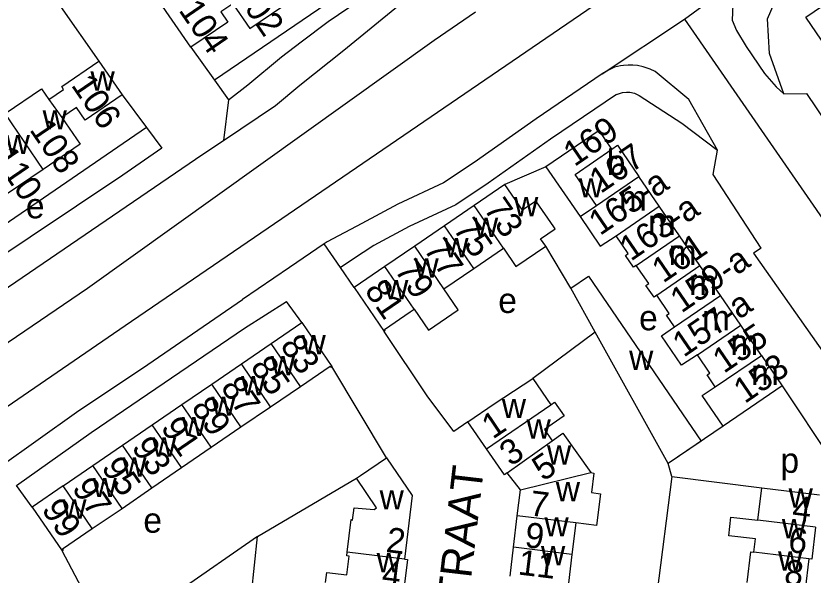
# Model space of a CAD drawing. Extents: x 157569 to 159501, y 382907 to 384670.
# Drawn here: x 158251.5 to 158378.5, y 383372.1 to 383461.2 of the extents above; entities that cross this region are included whole.
import ezdxf

# ---------------------------------------------------------------- set-up
doc = ezdxf.new("R2010")
doc.units = 0
for name, color, linetype in [('BLT_Basislijn', 7, 'Continuous'), ('BLT_Bebouwing', 7, 'Continuous'), ('BLT_Centroide', 7, 'Continuous'), ('BLT_Huisnummer', 7, 'Continuous'), ('BLT_Huisnummer_ tussenligend', 7, 'Continuous'), ('BLT_Huisnummer_reeks', 7, 'Continuous'), ('BLT_Onderverdeling_panden', 7, 'Continuous'), ('BLT_Straatnaam', 7, 'Continuous'), ('BLT_Vlakafsluiter', 7, 'Continuous')]:
    doc.layers.add(name, color=color, linetype=linetype)

msp = doc.modelspace()

# ---------------------------------------------------------------- linework, layer by layer
at = {"layer": 'BLT_Basislijn'}
for p, q in [((158268.87, 383411.85), (158344.6, 383463.62)), ((158358.02, 383460.71), (158395.45, 383406.45)), ((158268.41, 383448.63), (158272.26, 383443.46)), ((158285.33, 383447.86), (158284.53, 383441.35)), ((158272.26, 383443.46), (158229.21, 383413.95)), ((158272.26, 383443.46), (158274.71, 383440.16)), ((158335.92, 383437.19), (158329.36, 383434.34)), ((158303.19, 383421.09), (158300.61, 383424.9)), ((158339.89, 383417.82), (158335.88, 383424.52)), ((158305.35, 383417.9), (158303.19, 383421.09)), ((158297.04, 383412.33), (158294.59, 383415.71)), ((158343.78, 383410.81), (158333.82, 383403.43)), ((158310.53, 383390.76), (158301.83, 383405.34)), ((158373.58, 383402.22), (158383.14, 383387.77)), ((158364.17, 383395.83), (158355.41, 383389.85)), ((158355.97, 383387.8), (158355.41, 383389.85)), ((158289.96, 383378.2), (158305.74, 383387.52)), ((158355.97, 383387.8), (158345.24, 383302.74)), ((158355.97, 383387.8), (158370.3, 383385.97)), ((158254.07, 383382.91), (158251.55, 383386.37)), ((158288.29, 383362.43), (158289.96, 383378.2)), ((158264.43, 383365.32), (158258.86, 383375.92))]:
    msp.add_line(p, q, dxfattribs=at)
for points in [[(158285.33, 383447.86), (158288.45, 383450.24), (158293.8, 383454.7), (158296.92, 383457.08), (158301.23, 383460.35), (158320.69, 383473.57), (158328.86, 383479.81), (158330.2, 383481.6), (158330.5, 383484.12), (158328.86, 383492.74), (158329.57, 383494.21)], [(158328.23, 383488.92), (158329.02, 383482.29), (158283.13, 383450.96)], [(158284.53, 383441.35), (158292.81, 383446.92), (158296.69, 383450.16), (158303.7, 383455.76), (158312.43, 383462.88), (158315.66, 383465.79), (158332.42, 383477.98)], [(158251.08, 383470.55), (158252.5, 383471.5), (158264.68, 383454)], [(158368.7, 383468.6), (158367.49, 383467.29), (158366.26, 383465.41), (158365.68, 383463.03), (158365.61, 383460.57), (158366.26, 383458.9), (158367.85, 383456.37), (158370.74, 383452.03), (158372.62, 383449.93), (158373.85, 383448.78)], [(158373.85, 383448.78), (158371.56, 383455.24), (158371.21, 383460.74), (158372.45, 383463.58), (158373.64, 383464.73)], [(158262.9, 383417.82), (158318.11, 383457.34), (158324.71, 383461.89)], [(158279.37, 383456.24), (158283.13, 383450.96)], [(158353.35, 383452.34), (158352.55, 383452.72), (158351.4, 383453.1), (158350.49, 383453.3), (158349.78, 383453.38), (158349.01, 383453.38), (158348.3, 383453.34), (158347.8, 383453.28), (158346.87, 383453.04), (158346.4, 383452.86), (158345.87, 383452.59), (158344.89, 383451.99)], [(158363.23, 383439.81), (158358.69, 383447.92), (158353.35, 383452.34)], [(158283.13, 383450.96), (158285.33, 383447.86)], [(158344.89, 383451.99), (158334.37, 383444.84), (158324.48, 383437.86), (158319.61, 383434.62), (158312.32, 383431.21), (158306.58, 383428.12)], [(158347.14, 383448.68), (158336.64, 383441.55), (158326.74, 383434.56), (158321.58, 383431.12), (158314.11, 383427.64), (158308.48, 383424.6)], [(158347.14, 383448.68), (158348.11, 383449.04), (158348.74, 383449.07), (158349.28, 383449.07), (158350.01, 383448.92), (158350.76, 383448.55)], [(158350.76, 383448.55), (158357.59, 383444.14), (158363.23, 383439.81)], [(158373.85, 383448.78), (158377.46, 383448.87)], [(158377.46, 383448.87), (158385.58, 383436.8), (158387.08, 383434.08), (158401.15, 383413.79), (158401.36, 383413.55)], [(158281.28, 383439.16), (158284.53, 383441.35)], [(158274.71, 383440.16), (158268.52, 383435.84), (158231.56, 383411.11)], [(158370.2, 383424.2), (158362.58, 383435.92), (158363.23, 383439.81)], [(158191.06, 383377.09), (158244.7, 383414.23), (158281.28, 383439.16)], [(158306.58, 383428.12), (158301.08, 383425.22), (158300.61, 383424.9)], [(158300.61, 383424.9), (158295.08, 383421.12), (158287.59, 383416.02)], [(158308.48, 383424.6), (158306.79, 383423.5), (158303.19, 383421.09)], [(158370.2, 383424.2), (158369, 383423.38)], [(158369, 383423.38), (158386.7, 383398.24), (158386.5, 383396.7), (158383.14, 383387.77)], [(158094.46, 383303.58), (158123.76, 383323.12), (158150.88, 383341.57), (158262.9, 383417.82)], [(158261.15, 383398.07), (158272.49, 383405.62), (158287.59, 383416.02)], [(158263.46, 383394.8), (158287.89, 383411.42), (158294.59, 383415.71)], [(158100.7, 383295.99), (158125.39, 383313.08), (158140.85, 383323.93), (158268.87, 383411.85)], [(158323.49, 383396.53), (158321.27, 383394.94), (158316.98, 383400.65), (158310.13, 383410.92)], [(158131.9, 383308.9), (158138.33, 383313.42), (158187.3, 383347.02), (158228.07, 383374.98), (158248.84, 383389.35), (158261.15, 383398.07)], [(158251.55, 383386.37), (158263.46, 383394.8)], [(158289.96, 383378.2), (158277.29, 383369.4), (158274.72, 383365.15), (158273.9, 383364.16)]]:
    msp.add_lwpolyline(points, dxfattribs=at)
at = {"layer": 'BLT_Bebouwing'}
for p, q in [((158279.37, 383456.24), (158273.85, 383464.21)), ((158335.92, 383437.19), (158341.36, 383429.22)), ((158255.83, 383436.75), (158249.95, 383432.73)), ((158353.98, 383430.89), (158350.74, 383435.64)), ((158329.36, 383434.34), (158324.49, 383431.01)), ((158324.49, 383431.01), (158319.75, 383427.76)), ((158357.21, 383426.17), (158353.98, 383430.89)), ((158319.75, 383427.76), (158315.02, 383424.52)), ((158360.46, 383421.41), (158357.21, 383426.17)), ((158315.02, 383424.52), (158310.28, 383421.27)), ((158324.41, 383420.96), (158329.15, 383424.2)), ((158310.28, 383421.27), (158305.35, 383417.9)), ((158319.67, 383417.71), (158324.41, 383420.96)), ((158363.71, 383416.66), (158360.46, 383421.41)), ((158305.35, 383417.9), (158310.13, 383410.92)), ((158343.78, 383410.81), (158339.89, 383417.82)), ((158366.96, 383411.9), (158363.71, 383416.66)), ((158370.25, 383407.09), (158366.96, 383411.9)), ((158355.41, 383389.85), (158343.78, 383410.81)), ((158287.4, 383405.73), (158292.14, 383408.97)), ((158370.25, 383407.09), (158373.58, 383402.22)), ((158282.67, 383402.49), (158287.4, 383405.73)), ((158333.82, 383403.43), (158336.71, 383399.23)), ((158277.93, 383399.25), (158282.67, 383402.49)), ((158292.06, 383398.92), (158296.8, 383402.16)), ((158273.2, 383396), (158277.93, 383399.25)), ((158287.33, 383395.68), (158292.06, 383398.92)), ((158326.47, 383392.21), (158323.49, 383396.53)), ((158268.46, 383392.76), (158273.2, 383396)), ((158282.59, 383392.44), (158287.33, 383395.68)), ((158263.73, 383389.52), (158268.46, 383392.76)), ((158360.65, 383393.44), (158355.41, 383389.85)), ((158277.86, 383389.2), (158282.59, 383392.44)), ((158258.99, 383386.28), (158263.73, 383389.52)), ((158273.12, 383385.96), (158277.86, 383389.2)), ((158331.87, 383385.68), (158329.76, 383388.37)), ((158268.39, 383382.71), (158273.12, 383385.96)), ((158331.36, 383381.51), (158331.87, 383385.68)), ((158369.67, 383380.85), (158370.3, 383385.97)), ((158370.3, 383385.97), (158379.51, 383384.84)), ((158263.65, 383379.47), (158268.39, 383382.71)), ((158330.75, 383376.5), (158331.36, 383381.51)), ((158340.67, 383380.38), (158340.06, 383375.37)), ((158330.2, 383371.91), (158330.75, 383376.5)), ((158340.06, 383375.37), (158339.5, 383370.78)), ((158377.82, 383374.66), (158377.22, 383369.76))]:
    msp.add_line(p, q, dxfattribs=at)
for points in [[(158380.64, 383456.2), (158377.33, 383461.04), (158384.13, 383465.7), (158387.08, 383461.39), (158387.44, 383460.86)], [(158286.02, 383463.18), (158284.12, 383461.87), (158285.22, 383460.25), (158279.37, 383456.24)], [(158286.02, 383463.18), (158288.75, 383459.2), (158293.82, 383462.68)], [(158256.72, 383447.9), (158259.08, 383449.51), (158258.77, 383449.96), (158264.68, 383454)], [(158264.68, 383454), (158268.41, 383448.63)], [(158249.76, 383445.65), (158255.56, 383449.6), (158256.72, 383447.9)], [(158268.41, 383448.63), (158262.52, 383444.6), (158261.12, 383446.64), (158258.79, 383445.05)], [(158258.79, 383445.05), (158261.72, 383440.77), (158255.83, 383436.75)], [(158346.43, 383439.97), (158344.38, 383442.96), (158335.92, 383437.19)], [(158346.43, 383439.97), (158347.35, 383440.6), (158350.74, 383435.64)], [(158335.88, 383424.52), (158335.07, 383425.71), (158337.37, 383427.28), (158337.16, 383427.58), (158334.43, 383431.56), (158334.33, 383431.71), (158332.17, 383430.23), (158329.36, 383434.34)], [(158341.36, 383429.22), (158344.57, 383424.53), (158347.11, 383426.15)], [(158350.32, 383421.44), (158349.89, 383421.15), (158348.61, 383423.03), (158349.04, 383423.32), (158347.11, 383426.15)], [(158329.15, 383424.2), (158331.12, 383421.27), (158335.88, 383424.52)], [(158353.57, 383416.68), (158353.14, 383416.39), (158351.86, 383418.26), (158352.29, 383418.56), (158350.32, 383421.44)], [(158339.89, 383417.82), (158342.69, 383419.73), (158360.65, 383393.44)], [(158314.93, 383414.47), (158317.19, 383411.1), (158321.93, 383414.34), (158319.67, 383417.71)], [(158356.39, 383411.64), (158355.12, 383413.49), (158355.55, 383413.78), (158353.57, 383416.68)], [(158310.13, 383410.92), (158310.32, 383411.05), (158310.19, 383411.23), (158314.27, 383414.02), (158314.93, 383414.47)], [(158292.14, 383408.97), (158297.04, 383412.33)], [(158297.04, 383412.33), (158301.83, 383405.34)], [(158360.07, 383407.17), (158357.53, 383405.54), (158354.33, 383410.24), (158356.39, 383411.64)], [(158362.89, 383402.11), (158361.61, 383403.98), (158362.04, 383404.28), (158360.07, 383407.17)], [(158296.8, 383402.16), (158301.52, 383405.4), (158301.65, 383405.22), (158301.83, 383405.34)], [(158323.49, 383396.53), (158327.7, 383399.38), (158333.82, 383403.43)], [(158364.17, 383395.83), (158360.83, 383400.71), (158362.89, 383402.11)], [(158373.58, 383402.22), (158369.5, 383399.47), (158364.17, 383395.83)], [(158336.71, 383399.23), (158337.31, 383399.63), (158338.82, 383397.44), (158335.68, 383395.27), (158336.93, 383393.45)], [(158336.93, 383393.45), (158338.64, 383394.67), (158343.05, 383388.4)], [(158329.76, 383388.37), (158329.33, 383388.03), (158326.47, 383392.21)], [(158305.74, 383387.52), (158306.39, 383387.96), (158310.53, 383390.76)], [(158310.53, 383390.76), (158314.6, 383384.74), (158313.37, 383374.6)], [(158304.25, 383375.71), (158304.89, 383380.95), (158305.12, 383380.84), (158305.36, 383382.8), (158308.58, 383382.54), (158308.93, 383382.79), (158305.74, 383387.52)], [(158343.05, 383388.4), (158343.58, 383388.32), (158343.2, 383385.21), (158344.6, 383385.04), (158343.99, 383379.98), (158340.67, 383380.38)], [(158258.99, 383386.28), (158254.07, 383382.91)], [(158254.07, 383382.91), (158258.86, 383375.92)], [(158369.04, 383375.73), (158369.3, 383377.83), (158365.04, 383378.35), (158365.39, 383381.28), (158369.67, 383380.85)], [(158258.86, 383375.92), (158259.04, 383376.05), (158258.92, 383376.23), (158263.65, 383379.47)], [(158378.88, 383379.72), (158378.26, 383374.61), (158377.82, 383374.66)], [(158304.22, 383372.1), (158304.59, 383375.09), (158304.18, 383375.14), (158304.25, 383375.71)], [(158367.99, 383370.89), (158368.59, 383375.79), (158369.04, 383375.73)], [(158313.37, 383374.6), (158313.86, 383374.54), (158313.23, 383369.38)], [(158300.81, 383370.9), (158301, 383372.5), (158304.22, 383372.1)]]:
    msp.add_lwpolyline(points, dxfattribs=at)
at = {"layer": 'BLT_Onderverdeling_panden'}
for p, q in [((158256.72, 383447.9), (158258.79, 383445.05)), ((158255.83, 383436.75), (158249.76, 383445.65)), ((158343.97, 383431), (158350.74, 383435.64)), ((158329.15, 383424.2), (158324.49, 383431.01)), ((158341.36, 383429.22), (158343.97, 383431)), ((158347.11, 383426.15), (158353.98, 383430.89)), ((158324.41, 383420.96), (158319.75, 383427.76)), ((158350.32, 383421.44), (158357.21, 383426.17)), ((158319.67, 383417.71), (158315.02, 383424.52)), ((158314.93, 383414.47), (158310.28, 383421.27)), ((158353.57, 383416.68), (158360.46, 383421.41)), ((158356.39, 383411.64), (158363.71, 383416.66)), ((158360.07, 383407.17), (158366.96, 383411.9)), ((158296.8, 383402.16), (158292.14, 383408.97)), ((158362.89, 383402.11), (158370.25, 383407.09)), ((158292.06, 383398.92), (158287.4, 383405.73)), ((158287.33, 383395.68), (158282.67, 383402.49)), ((158282.59, 383392.44), (158277.93, 383399.25)), ((158326.47, 383392.21), (158336.71, 383399.23)), ((158277.86, 383389.2), (158273.2, 383396)), ((158273.12, 383385.96), (158268.46, 383392.76)), ((158329.76, 383388.37), (158336.93, 383393.45)), ((158268.39, 383382.71), (158263.73, 383389.52)), ((158331.87, 383385.68), (158343.05, 383388.4)), ((158263.65, 383379.47), (158258.99, 383386.28)), ((158340.67, 383380.38), (158331.36, 383381.51)), ((158378.88, 383379.72), (158369.67, 383380.85)), ((158340.06, 383375.37), (158330.75, 383376.5)), ((158313.37, 383374.6), (158304.25, 383375.71)), ((158377.82, 383374.66), (158369.04, 383375.73))]:
    msp.add_line(p, q, dxfattribs=at)
msp.add_lwpolyline([(158343.97, 383431), (158340.58, 383435.94), (158346.43, 383439.97)], dxfattribs=at)
at = {"layer": 'BLT_Vlakafsluiter'}
for p, q in [((158358.02, 383460.71), (158368.7, 383468.6)), ((158344.89, 383451.99), (158358.02, 383460.71))]:
    msp.add_line(p, q, dxfattribs=at)

# ---------------------------------------------------------------- texts
at = {"layer": 'BLT_Centroide'}
for s, p in [('w', (158263.36, 383449.31)), ('w', (158255.73, 383443.12)), ('w', (158249.84, 383439.19)), ('b', (158345.62, 383435.88)), ('w', (158341.17, 383432.28)), ('m', (158347.55, 383430.19)), ('e', (158253.06, 383428.95)), ('w', (158330.84, 383429.28)), ('m', (158352.18, 383426.31)), ('w', (158324.45, 383425.98)), ('w', (158319.72, 383422.73)), ('m', (158355.46, 383421.53)), ('w', (158314.97, 383419.5)), ('w', (158310.14, 383416.06)), ('m', (158358.74, 383416.72)), ('e', (158328.33, 383413.86)), ('e', (158350.76, 383411.1)), ('m', (158360.78, 383411.09)), ('w', (158296.98, 383407.28)), ('m', (158365.3, 383407.16)), ('w', (158349.17, 383404.79)), ('w', (158292.09, 383403.94)), ('m', (158368.59, 383402.38)), ('w', (158287.36, 383400.72)), ('w', (158282.62, 383397.47)), ('w', (158328.89, 383397.09)), ('w', (158277.89, 383394.22)), ('w', (158332.83, 383393.84)), ('w', (158273.16, 383390.97)), ('w', (158336.09, 383389.69)), ('p', (158373.28, 383388.37)), ('w', (158268.42, 383387.75)), ('w', (158263.69, 383384.5)), ('w', (158337.49, 383383.84)), ('w', (158309.42, 383382.53)), ('w', (158374.59, 383382.84)), ('w', (158258.86, 383381.06)), ('e', (158271.78, 383378.82)), ('w', (158335.69, 383378.22)), ('w', (158373.51, 383377.94)), ('w', (158335.13, 383373.62)), ('w', (158308.95, 383372.53)), ('w', (158372.91, 383372.78))]:
    msp.add_text(s, height=4, dxfattribs=at).set_placement(p)
at = {"layer": 'BLT_Huisnummer'}
for s, rotation, p in [('104', 304.4625, (158277.31, 383462.14)), ('106', 304.337, (158260.18, 383450.19)), ('169', 34.3704, (158340.47, 383437.1)), ('167', 34.4194, (158344.63, 383432.8)), ('110', 304.337, (158247.62, 383438.75)), ('73', 304.3704, (158325.91, 383430.47)), ('77', 304.3704, (158316.34, 383424.02)), ('161', 34.4194, (158354.59, 383418.53)), ('81', 304.3704, (158306.92, 383417.46)), ('83', 304.3933, (158293.48, 383408.67)), ('153', 34.4194, (158367.6, 383399.32)), ('87', 304.3933, (158284, 383402.01)), ('1', 34.0262, (158327.45, 383393.65)), ('91', 304.3933, (158274.45, 383395.58)), ('5', 34.0262, (158335.48, 383386.92)), ('95', 304.3933, (158264.99, 383389.21)), ('99', 304.3933, (158255.46, 383382.54)), ('4', 353.0408, (158375.03, 383380.83)), ('9', 353.0667, (158332.42, 383376.55)), ('8', 353.0408, (158373.75, 383370.65))]:
    msp.add_text(s, height=4, rotation=rotation, dxfattribs=at).set_placement(p)
at = {"layer": 'BLT_Huisnummer_ tussenligend'}
for s, rotation, p in [('102', 304.4693, (158286.08, 383465)), ('108', 304.337, (158253.55, 383443.08)), ('75', 304.3704, (158321.04, 383427.27)), ('79', 304.3704, (158311.71, 383420.69)), ('155', 34.4194, (158364.27, 383404.13)), ('85', 304.3933, (158288.73, 383405.29)), ('89', 304.3933, (158279.31, 383398.79)), ('93', 304.3933, (158269.8, 383392.44)), ('3', 34.0262, (158330.29, 383389.3)), ('97', 304.3933, (158260.3, 383385.9)), ('7', 353.0667, (158333.19, 383381.6)), ('2', 353.0574, (158310.32, 383375.76)), ('6', 353.0408, (158374.38, 383375.77)), ('11', 353.0667, (158331.35, 383372.18)), ('4', 353.0574, (158309.65, 383370.47))]:
    msp.add_text(s, height=4, rotation=rotation, dxfattribs=at).set_placement(p)
at = {"layer": 'BLT_Huisnummer_reeks'}
for s, rotation, p in [('165-a', 34.4194, (158344.53, 383426.1)), ('163-a', 34.4194, (158349.45, 383422.02)), ('159-a', 34.4244, (158357.51, 383413.75)), ('157-a', 34.4194, (158357.87, 383406.7))]:
    msp.add_text(s, height=4, rotation=rotation, dxfattribs=at).set_placement(p)
at = {"layer": 'BLT_Straatnaam'}
msp.add_text('STEENBERGENSTRAAT', height=5, rotation=83.3526, dxfattribs=at).set_placement((158317.16, 383312.79))

doc.saveas('drawing.dxf')
